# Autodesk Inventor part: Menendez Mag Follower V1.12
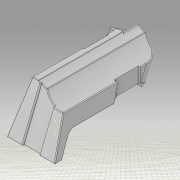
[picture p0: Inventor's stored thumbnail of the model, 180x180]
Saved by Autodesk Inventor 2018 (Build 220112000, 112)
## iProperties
Created: 2019-06
Part Number: Menendez Mag Follower V1.12
Material: Generic
Document SubType Name: Modeling
Designer: Ivan
Density: 1 g/cm^3
Appearance: Default
Author: Ivan
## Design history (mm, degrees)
sketch "Sketch1"
  geometry: L1 (0, 0)-(10.77, 0); L2 (10.77, 0)-(10.77, -30.556); L3 (10.77, -30.556)-(0, -30.556); L4 (0, -30.556)-(0, 0)
  constraints: 8 end point, 2 parallel, 1 horizontal, 1 perpendicular
  dimensions: "d0" = 10.7696 distance of L2.end L3.end; "d1" = 30.5562 distance of L1.end L2.end
extrude "Extrusion1" new body sketch "Sketch1" distance "d2" = 8.5344; taper "d3" = 0 deg
sketch "Sketch2"
  geometry: L1 (0, 0)-(3.287, 8.135); L2 (0, 0)-(8.774, 0); L3 (3.287, 8.135)-(3.448, 8.534); L4 (0, 8.534)-(30.556, 8.534) reference; L5 (30.556, 0)-(30.556, 8.534) reference; L6 (30.556, 8.534)-(27.343, 0.582); L7 (30.556, 8.534)-(39.133, 8.534); L8 (27.343, 0.582)-(27.108, 0); L9 (30.556, 0)-(0, 0) reference; L10 (0, 0)-(0, 8.534) reference; L11 (0, 8.534)-(0, 0)
  constraints: 14 end point, 4 point on line, 2 equal length, 2 horizontal, 1 collinear
  dimensions: "d4" = 68 deg angle of L2 L1; "d5" = 112 deg angle of L6 L7
workplane "Work Plane2"
workplane "Work Plane1"
sketch "Sketch7"
  geometry: L1 (30.556, -8.534)-(0, -8.534) reference; L2 (13.161, -8.534)-(13.161, -3.886); L3 (27.108, 0)-(30.556, -8.534) reference; L4 (27.108, 0)-(33.236, -15.167) reference; L5 (0, 0)-(30.556, 0) reference; L6 (13.161, -3.886)-(19.98, -3.886); L7 (16.616, 0)-(17.43, -2.015); L8 (17.43, -2.015)-(18.186, -3.886); L9 (30.556, 0)-(0, 0) reference; L10 (16.616, 0)-(27.108, 0); L11 (18.186, -3.886)-(28.678, -3.886); L12 (27.108, 0)-(28.678, -3.886); L13 (28.678, -3.886)-(12.524, -3.886); L14 (12.524, -3.886)-(12.885, -4.78); L15 (12.885, -4.78)-(14.232, -8.114); L16 (0, -8.534)-(30.556, -8.534) reference; L17 (14.402, -8.534)-(14.232, -8.114); L18 (14.402, -8.534)-(30.556, -8.534); L19 (30.556, -8.534)-(28.678, -3.886); 1 further point
  constraints: 26 end point, 5 collinear, 4 point on line, 3 parallel, 2 horizontal, 1 vertical
  dimensions: "d18" = 4.6482 distance of L2.start L2.end; "d20" = 16.1544 distance of L11.end L13.end
sketch "Sketch8"
  geometry: L1 (0, 8.534)-(10.77, 8.534) reference; L2 (5.385, 8.534)-(5.385, -8.103); L3 (5.385, -8.103)-(-2.515, -8.103); L4 (-2.515, -8.103)-(0, 8.534); L5 (-2.515, -8.103)-(0, 8.534); L6 (0, 8.534)-(5.385, 8.534); 1 further point
  constraints: 10 end point, 2 collinear, 1 midpoint, 1 perpendicular, 1 vertical
  dimensions: "d21" = 16.637 distance of L2.start L2.end; "d22" = 7.8994 distance of L2.end L3.end
extrude "Extrusion6" join sketch "Sketch8" distance "d23" = 19.558; taper "d24" = 0 deg
sketch "Sketch11"
  geometry: L1 (18.032, -1.719)-(27.922, -1.719); L2 (27.922, -1.719)-(27.922, 21.577); L3 (27.922, 21.577)-(18.032, 21.577); L4 (18.032, 21.577)-(18.032, -1.719); 1 further point
  constraints: 8 end point, 2 parallel, 1 horizontal, 1 perpendicular
extrude "Extrusion7" join sketch "Sketch11" distance "d25" = 16.129; taper "d26" = 0 deg
sketch "Sketch12"
  geometry: L1 (10.258, 5.653)-(-17.984, 5.653); L2 (-17.984, 5.653)-(-17.984, -21.463); L3 (-17.984, -21.463)-(10.258, -21.463); L4 (10.258, -21.463)-(10.258, 5.653); 1 further point
  constraints: 8 end point, 2 parallel, 1 horizontal, 1 perpendicular
extrude "Extrusion8" cut sketch "Sketch12" distance "d27" = 16.129; taper "d28" = 0 deg
sketch "Sketch13"
  geometry: L1 (-12.767, -9.49)-(31.439, -9.49); L2 (31.439, -9.49)-(31.439, 48.574); L3 (31.439, 48.574)-(-12.767, 48.574); L4 (-12.767, 48.574)-(-12.767, -9.49); 1 further point
  constraints: 8 end point, 2 parallel, 1 horizontal, 1 perpendicular
extrude "Extrusion9" cut sketch "Sketch13" distance "d29" = 16.129; taper "d30" = 0 deg
sketch "Sketch14"
  geometry: L1 (0, 0)-(8.413, 0) reference; L2 (8.413, 0)-(8.413, 8.103) reference; L3 (3.028, 8.103)-(8.413, 8.103) reference; L4 (3.028, 8.103)-(3.028, 16.637) reference; L5 (3.028, 16.637)-(-2.515, 16.637) reference; L6 (0, 0)-(-2.515, 16.637) reference; 1 further point
extrude "Extrusion10" cut sketch "Sketch14" distance "d31" = 16.129; taper "d32" = 0 deg
sketch "Sketch16"
  geometry: L1 (-6.479, 4.169)-(15.928, 4.169); L2 (15.928, 4.169)-(15.928, -19.738); L3 (15.928, -19.738)-(-6.479, -19.738); L4 (-6.479, -19.738)-(-6.479, 4.169); 1 further point
  constraints: 8 end point, 2 parallel, 1 horizontal, 1 perpendicular
extrude "Extrusion11" cut sketch "Sketch16" stored distance "d33" = 16.129; taper "d34" = 0 deg
sketch "Sketch18"
  geometry: L1 (-21.306, 0)-(-14.584, 16.637) reference; L2 (-21.306, 0)-(-19.147, 0); L3 (1.526, 0)-(-21.306, 0) reference; L4 (-17.563, 9.263)-(-14.69, 8.103); L5 (-18.032, 8.103)-(-21.306, 0) reference; L6 (12.524, 8.103)-(-18.032, 8.103) reference; L7 (-14.69, 8.103)-(-19.147, 0); L8 (-14.69, 8.103)-(0, 8.103); L9 (0, 8.103)-(0, 0) reference; L10 (0, 0)-(0, 8.103); L11 (0, 8.103)-(0, 0); L12 (0, 0)-(-19.147, 0)
  constraints: 14 end point, 4 point on line, 3 perpendicular, 1 collinear
  dimensions: "d35" = 2.159 distance of L1.start L2.end; "d36" = 3.0988 distance of L4.start L4.end
extrude "Extrusion12" cut sketch "Sketch18" distance "d37" = 16.129; taper "d38" = 0 deg
sketch "Sketch19"
  geometry: L1 (12.524, 0)-(27.214, 0) reference; L2 (27.108, 8.534)-(30.556, 0) reference; L3 (12.524, 4.445)-(28.76, 4.445); L4 (27.108, 8.534)-(0, 8.534) reference; L5 (26.182, 12.255)-(16.973, 8.534); L6 (16.973, 8.534)-(18.626, 4.445); L7 (16.973, 8.534)-(27.108, 8.534); L8 (27.108, 8.534)-(28.76, 4.445); L9 (16.973, 8.534)-(12.524, 8.534); L10 (12.524, 4.445)-(6.405, 4.445); L11 (11.337, 4.445)-(13.133, 0); L12 (0, 0)-(30.556, 0) reference; L13 (21.459, 8.534)-(26.315, 10.497); L14 (13.133, 0)-(10.5, 0); L15 (10.5, 0)-(10.5, 8.534); L16 (16.973, 8.534)-(10.5, 8.534); 1 further point
  constraints: 24 end point, 8 point on line, 4 perpendicular, 3 horizontal, 2 collinear, 2 parallel
  dimensions: "d39" = 4.445 distance of L1.start L3.start; "d40" = 9.9314 distance of L5.start L5.end; "d101" = 16.1544 distance of L11.start L13.end
extrude "Extrusion13" cut sketch "Sketch19" distance "d41" = 16.129; taper "d42" = 0 deg
extrude "Extrusion14" cut sketch "Sketch2" distance "d43" = 25.4; taper "d44" = 0 deg
workplane "Work Plane3"
mirror "Mirror1"
sketch "Sketch20"
  geometry: L1 (0, 0)-(1.115, -2.026) reference; L2 (3.274, -2.026)-(1.115, -2.026) reference; L3 (3.274, -2.026)-(0, 6.076) reference; L4 (0, 0)-(0, 6.076) reference; 1 further point
extrude "Extrusion15" join sketch "Sketch20" stored distance "d45" = 25.4; taper "d46" = 0 deg
sketch "Sketch21"
  geometry: L1 (12.894, 0.193)-(12.894, 0) reference; L2 (12.894, 0)-(16.342, 8.631); L3 (12.894, 0)-(14.69, 4.495) reference; L4 (8.588, 4.495)-(14.69, 4.495); L5 (15.877, 4.588)-(8.588, 4.588) reference; L6 (10.241, 8.631)-(16.342, 8.631); L7 (15.877, 4.495)-(8.588, 4.495) reference; L8 (8.588, 4.495)-(14.69, 4.495); L9 (14.69, 4.495)-(16.342, 8.631); L10 (16.342, 8.631)-(10.241, 8.631); L11 (8.588, 4.495)-(7.662, 4.495); L12 (7.662, 4.495)-(9.218, 8.631); L13 (0.106, 8.631)-(10.241, 8.631) reference; L14 (10.241, 8.631)-(9.218, 8.631); 6 further points; 1 other entity
  constraints: 18 end point, 3 horizontal, 3 parallel, 1 collinear, 1 point on line, 2 other
extrude "Extrusion16" join sketch "Sketch21" stored distance "d47" = 25.4; taper "d48" = 0 deg
sketch "Sketch22"
  geometry: L1 (1.758, 4.352)-(1.796, 4.445) reference; L2 (0, 0)-(1.796, 4.445) reference; L3 (0, 0)-(1.758, 4.352) reference; L4 (0, 0)-(1.796, 4.445) reference; L5 (0, 0)-(4.134, 10.233); L6 (4.134, 10.233)-(4.816, 9.16); L7 (4.816, 9.16)-(4.134, 2.45); L8 (1.187, 0)-(-12.894, 0) reference; L9 (4.134, 2.45)-(0, 0); 2 further points
  constraints: 8 end point, 1 collinear
extrude "Extrusion17" cut sketch "Sketch22" distance "d49" = 25.4; taper "d50" = 0 deg
workplane "Work Plane4"
sketch "Sketch23"
  geometry: L1 (-5.715, -4.089)-(-5.715, 0) reference; L2 (-5.715, 0)-(-3.683, 0); L3 (-5.715, 0)-(5.055, 0) reference; L4 (-3.683, 0)-(-3.683, -1.016); L5 (-3.683, -1.016)-(-1.016, -1.016); L6 (-1.016, -1.016)-(-1.016, -3.556); L7 (6.345, -8.534)-(5.055, 0) reference; L8 (5.592, -3.556)-(5.055, 0); L9 (5.055, 0)-(-3.683, 0); L10 (5.055, 0)-(-5.715, 0) reference; A1 r 4.215 centre (-0.938, 3.198) between (-3.683, 0) and (-1.016, -1.016); A2 r 6.35 centre (4.18, 2.635) between (-1.016, -1.016) and (5.592, -3.556); 2 further points
  constraints: 12 end point, 4 point on circle, 2 centre point, 2 collinear, 2 perpendicular, 2 point on line, 1 vertical
  dimensions: "d52" = 2.032 distance of L1.end L2.end; "d53" = 1.016 distance of L2.end L4.end; "d54" = 2.667 distance of L4.end L5.end; "d55" = 2.54 distance of L5.end L6.end; "d56" = 6.35 radius of A2
extrude "Extrusion18" cut sketch "Sketch23" stored distance "d57" = 76.2; taper "d58" = 0 deg
fillet "Fillet1" dims "d59" = 1.016
sketch "Sketch25"
  geometry: L1 (9.054, -4.88)-(9.054, -8.08) reference; L2 (9.054, -4.88)-(6.98, -10.013); L3 (9.054, -4.88)-(11.026, 0) reference; L4 (7.761, -8.08)-(9.054, -8.08); L5 (9.054, -4.88)-(8.013, -4.88) reference; L6 (9.054, -4.88)-(9.054, -8.08); L7 (7.761, -8.08)-(3.392, -8.08); L8 (3.392, -8.08)-(4.685, -4.88); L9 (9.054, -4.88)-(-0.631, -4.88) reference; L10 (-0.631, -4.88)-(9.054, -4.88) reference; L11 (4.685, -4.88)-(9.054, -4.88); 3 further points
  constraints: 12 end point, 3 collinear, 2 horizontal, 2 point on line, 1 parallel
  dimensions: "d66" = 4.3688 distance of L4.start L7.end
sketch "Sketch26"
  geometry: 1 further point
extrude "Extrusion20" join sketch "Sketch25" stored distance "d67" = 10.16; taper "d68" = 0 deg
sketch "Sketch27"
  geometry: L1 (3.392, -8.08)-(7.761, -8.08) reference; L2 (7.761, -8.08)-(6.72, -8.08); L3 (-0.631, -4.88)-(4.685, -4.88) reference; L4 (4.685, -4.88)-(3.392, -8.08); A1 r 3.227 centre (3.499, -7.881) between (6.72, -8.08) and (4.685, -4.88); 3 further points
  constraints: 4 end point, 2 point on circle, 1 centre point, 1 point on line
  dimensions: "d69" = 1.0414 distance of L1.end L2.end
extrude "Extrusion21" cut sketch "Sketch27" stored distance "d70" = 10.16; taper "d71" = 0 deg
workplane "Work Plane5"
sketch "Sketch32"
  geometry: L1 (-8.737, 0)-(6.64, 0) reference; L2 (-1.048, 0)-(1.492, 0); L3 (1.492, 0)-(-3.588, 0); L4 (-3.588, 0)-(-3.588, -0.381); L5 (1.492, 0)-(1.492, -0.381); L6 (1.492, -0.381)-(-3.588, -0.381); 3 further points
  constraints: 10 end point, 2 perpendicular, 2 point on line, 1 midpoint, 1 vertical
  dimensions: "d86" = 2.54 distance of L2.start L2.end; "d87" = 5.08 distance of L2.end L3.end; "d88" = 0.381 distance of L3.end L4.end
extrude "Extrusion26" cut sketch "Sketch32" stored distance "d89" = 50.8; taper "d90" = 0 deg
fillet "Fillet3" dims "d91" = 0.3556
workplane "Work Plane6"
sketch "Sketch36"
  geometry: L1 (-0.044, -8.686)-(1.937, -8.686); L2 (1.937, -8.686)-(1.937, 0); L3 (1.937, 0)-(-0.044, 0); L4 (-0.044, 0)-(-0.044, -8.686); 1 further point
  constraints: 8 end point, 2 parallel, 1 horizontal, 1 perpendicular
extrude "Extrusion29" cut sketch "Sketch36" stored distance "d102" = 50.8; taper "d103" = 0 deg
sketch "Sketch37"
  geometry: L1 (-0.785, -4.88)-(-0.411, -3.955) reference; L2 (-0.785, -4.88)-(1.189, 0.005); L3 (-1.972, -4.88)-(0.04, 0.099) reference; L4 (0.04, 0.099)-(-16.197, 0.099) reference; L5 (0.04, 0.099)-(1.226, 0.099); L6 (1.226, 0.099)-(1.189, 0.005); L7 (0, 0)-(-1.972, -4.88) reference; L8 (0.04, 0.099)-(-1.972, -4.88); L9 (-0.785, -4.88)-(-1.972, -4.88); L10 (-0.785, -4.88)-(-14.866, -4.88) reference; 1 further point
  constraints: 10 end point, 2 collinear, 1 horizontal, 1 parallel
extrude "Extrusion30" join sketch "Sketch37" stored distance "d104" = 50.8; taper "d105" = 0 deg
sketch "Sketch39"
  geometry: L1 (5.055, -3.556)-(5.592, -3.556) reference; L2 (5.055, -3.556)-(5.055, -3.655) reference; A1 r 6.35 centre (4.18, 2.635) between (5.055, -3.655) and (5.592, -3.556) reference; 1 further point
extrude "Extrusion31" cut sketch "Sketch39" stored distance "d106" = 50.8; taper "d107" = 0 deg
workplane "Work Plane7"
sketch "Sketch40"
  geometry: L1 (0, 0)-(0, -8.08) reference; L2 (0, 0)-(10.77, 0) reference; L3 (10.77, -11.735)-(10.77, 0) reference; L4 (8.738, -11.735)-(10.77, -11.735) reference; A1 r 6.35 centre (0.875, -14.37) between (6.071, -10.719) and (0, -8.08) reference; A2 r 4.215 centre (5.992, -14.933) between (8.738, -11.735) and (6.071, -10.719) reference; 1 further point
extrude "Extrusion32" join sketch "Sketch40" distance "d109" = 50.8; taper "d110" = 0 deg
sketch "Sketch41"
  geometry: L1 (-15.412, 4.978)-(-20.132, -6.706) reference; L2 (-17.423, 0)-(9.895, -11.037); L3 (9.895, -11.037)-(23.131, 21.723); L4 (23.131, 21.723)-(63.294, 20.181); L5 (63.294, 20.181)-(80.698, -6.696); L6 (80.698, -6.696)-(73.206, -14.512); L7 (73.206, -14.512)-(25.524, -20.796); L8 (25.524, -20.796)-(9.895, -11.037)
  constraints: 14 end point, 2 perpendicular
  dimensions: "d111" = 29.464 distance of L2.start L2.end
extrude "Extrusion33" cut sketch "Sketch41" stored distance "d112" = 50.8; taper "d113" = 0 deg
sketch "Sketch42"
  geometry: L1 (7.351, -3.2)-(13.062, -3.2) reference; L2 (13.062, -3.2)-(12.02, -3.2); L3 (7.351, -3.2)-(11.64, -3.2); L4 (10.073, 0)-(5.316, 0); A1 r 3.227 centre (4.13, -3.001) between (7.351, -3.2) and (5.316, 0) reference; A2 r 3.175 centre (8.857, -2.933) between (12.02, -3.2) and (10.073, 0); 1 further point
  constraints: 6 end point, 2 horizontal, 2 point on circle, 1 centre point, 1 point on line
  dimensions: "d114" = 1.0414 distance of L1.end L2.end; "d115" = 3.175 radius of A2
extrude "Extrusion34" cut sketch "Sketch42" distance "d116" = 50.8; taper "d117" = 0 deg
sketch "Sketch43"
  geometry: 1 further point
sketch "Sketch44"
  geometry: L1 (6.851, -1.397)-(-8.948, -1.397) reference; L2 (-1.048, -1.046)-(-1.048, -28.498); L3 (-6.433, -28.498)-(4.336, -28.498) reference; L4 (-6.433, -25.494)-(-6.433, -16.154) reference; L5 (-6.433, -20.216)-(-5.392, -20.216); L6 (-5.392, -20.216)-(-5.392, -24.454); L7 (-5.392, -24.454)-(-5.392, -3.099); L8 (-7.723, -3.099)-(5.626, -3.099) reference; A1 r 6.35 centre (-0.708, -7.387) between (-1.048, -1.046) and (-5.392, -3.099); A2 r 6.35 centre (0.606, -22.368) between (-5.392, -24.454) and (-1.048, -28.498); 1 further point
  constraints: 8 end point, 4 point on circle, 3 point on line, 2 centre point, 1 midpoint, 1 perpendicular, 1 vertical
  dimensions: "d118" = 6.35 radius of A1; "d119" = 27.45233 distance of L2.end L2.start; "d120" = 6.35 radius of A2; "d148" = 1.0414 distance of L5.start L5.end
extrude "Extrusion35" cut sketch "Sketch44" stored distance "d121" = 50.8; taper "d122" = 0 deg
mirror "Mirror5"
sketch "Sketch45"
  geometry: L1 (-2.106, 2.085)-(4.203, 2.085) reference; A1 r 6.35 centre (1.388, 7.387) between (-2.106, 2.085) and (1.048, 1.046) reference; A2 r 6.35 centre (0.708, 7.387) between (1.048, 1.046) and (4.203, 2.085) reference; 1 further point
extrude "Extrusion36" cut sketch "Sketch45" distance "d123" = 50.8; taper "d124" = 0 deg
fillet "Fillet4" dims "d125" = 2.54
sketch "Sketch46"
  geometry: L1 (-11.266, -7.645)-(-14.531, 0.435) reference; L2 (-13.683, -1.662)-(-15.358, 2.483); L3 (-11.213, 4.157)-(-7.737, -4.445); L4 (1.796, -4.445)-(-8.277, -4.445) reference; L5 (15.771, 4.089)-(-16.007, 4.089) reference; L6 (-11.186, 4.089)-(-16.007, 4.089); L7 (-10.225, -7.645)-(-11.266, -7.645) reference; L8 (-16.007, 4.089)-(-11.266, -7.645); L9 (-11.266, -7.645)-(-10.225, -7.645); L10 (-7.737, -4.445)-(-8.277, -4.445); A1 r 3.175 centre (-7.061, -7.378) between (-8.277, -4.445) and (-10.225, -7.645); 1 further point
  constraints: 12 end point, 4 collinear, 4 point on line, 2 point on circle, 1 centre point
  dimensions: "d126" = 4.4704 distance of L2.start L2.end; "d127" = 4.4704 distance of L2.end L3.start
extrude "Extrusion37" join sketch "Sketch46" distance "d128" = 2.2098; taper "d129" = 0 deg
sketch "Sketch47"
  geometry: L1 (-10.77, 13.583)-(-10.77, 30.405) reference; L2 (-10.77, 30.405)-(-8.738, 30.405); L3 (-12.979, 30.485)-(0, 30.485) reference; L4 (-10.77, 30.405)-(-8.738, 30.405); L5 (-8.738, 3.448)-(-8.738, 35.226) reference; L6 (-8.738, 30.405)-(-8.738, 35.226); L7 (-12.979, 35.226)-(-12.979, 30.485) reference; L8 (-8.738, 35.226)-(-12.979, 35.226); L9 (-12.979, 35.226)-(-12.979, 30.405); L10 (-8.738, 35.226)-(-8.738, 30.908); L11 (-12.979, 30.405)-(-8.738, 30.405); L12 (-8.738, 30.405)-(-8.738, 35.226); L13 (-8.738, 35.226)-(-12.979, 35.226); L14 (-12.979, 35.226)-(-12.979, 30.405); 1 further point
  constraints: 20 end point, 3 parallel, 2 collinear, 2 horizontal, 2 point on line, 1 perpendicular
  dimensions: "d130" = 2.032 distance of L1.end L2.end; "d131" = 0 distance between parallel lines of L2 L4 (derived); "d132" = 4.318 distance of L5.end L10.end
workplane "Work Plane9"
  workplane "Work Plane8"
extrude "Extrusion38" cut sketch "Sketch47" stored distance "d135" = 1.778; taper "d136" = 0 deg
sketch "Sketch48"
  geometry: L1 (3.448, -7.332)-(0, 1.202) reference; L2 (0, 1.202)-(0, 0) reference; L3 (0, 0)-(0.418, 0.169); L4 (0, 1.202)-(0.406, 0.198); L5 (0.418, 0.169)-(0.371, 0.284); L6 (0, 1.202)-(-4.821, 1.202) reference; L7 (0, 1.202)-(0, 0); 1 further point
  constraints: 8 end point, 3 point on line, 2 perpendicular
extrude "Extrusion39" cut sketch "Sketch48" distance "d137" = 25.4; taper "d138" = 0 deg
fillet "Fillet5" dims "d139" = 4.572
fillet "Fillet7" dims "d141" = 0.254
fillet "Fillet8" dims "d142" = 0.254
fillet "Fillet9" dims "d143" = 0.254
sketch "Sketch49"
  geometry: L1 (-23.949, -12.767)-(-17.284, -12.767); L2 (-17.284, -12.767)-(-17.284, -10.862); L3 (-17.284, -10.862)-(-23.949, -10.862); L4 (-23.949, -10.862)-(-23.949, -12.767); 1 further point
  constraints: 8 end point, 2 parallel, 1 horizontal, 1 perpendicular
  dimensions: "d144" = 1.905 distance of L2.end L1.end
extrude "Extrusion40" cut sketch "Sketch49" stored distance "d145" = 27.94; taper "d146" = 0 deg
fillet "Fillet10" dims "d147" = 0.254
sketch "Sketch50"
  geometry: L1 (-0.254, 0)-(-0.254, -0.254) reference; L2 (1.778, 0)-(0, 0) reference; L3 (1.778, 0)-(1.778, 4.459) reference; L4 (-0.254, 0)-(-2.464, 0) reference; A1 r 0.254 centre (0, -0.254) between (0, 0) and (-0.254, -0.254) reference; A2 r 4.572 centre (2.107, -0.102) between (1.778, 4.459) and (-2.464, 0) reference; 1 further point
extrude "Extrusion41" cut sketch "Sketch50" distance "d149" = 0.508; taper "d150" = 0 deg
fillet "Fillet11" dims "d151" = 0.254
sketch "Sketch51"
  geometry: L1 (0, -19.253)-(-0.635, -19.253); L2 (-0.635, -19.253)-(-0.635, -26.95); L3 (-0.635, -26.95)-(0, -26.95); L4 (0, -26.95)-(0, -19.253); 3 further points; 1 other entity
  constraints: 8 end point, 2 parallel, 1 horizontal, 1 perpendicular, 1 other
  dimensions: "d152" = 0.635 distance of L3.end L2.end
extrude "Extrusion42" cut sketch "Sketch51" distance "d153" = 25.4; taper "d154" = 0 deg
mirror "Mirror6"
fillet "Fillet12" dims "d157" = 0.5334
fillet "Fillet13" dims "d158" = 0.381
sketch "Sketch53"
  geometry: L1 (-0.254, 0)-(-2.196, 0) reference; L2 (-0.254, -0.254)-(-0.254, 0) reference; L3 (1.778, 0)-(0, 0) reference; L4 (1.778, 4.459)-(1.778, 0) reference; A1 r 0.254 centre (-2.196, 0.254) between (-2.449, 0.275) and (-2.196, 0) reference; A2 r 0.254 centre (0, -0.254) between (0, 0) and (-0.254, -0.254) reference; A3 r 4.572 centre (2.107, -0.102) between (1.778, 4.459) and (-2.449, 0.275) reference; 1 further point
extrude "Extrusion44" join sketch "Sketch53" distance "d159" = 0.508; taper "d160" = 0 deg
sketch "Sketch54"
  geometry: L1 (-9.728, -4.645)-(-9.728, -27.671) reference; L2 (-9.728, -13.237)-(-8.392, -13.237); L3 (-8.392, -13.237)-(-8.392, -4.645); L4 (-8.392, -4.645)-(-9.728, -4.645); L5 (-9.728, -4.645)-(-9.728, -13.237); A1 r 7.614 centre (-3.441, -8.941) between (-9.728, -4.645) and (-9.728, -13.237); 1 further point
  constraints: 8 end point, 2 parallel, 2 point on circle, 1 centre point, 1 horizontal, 1 perpendicular, 1 point on line
extrude "Extrusion45" cut sketch "Sketch54" stored distance "d162" = 0.508; taper "d163" = 0 deg
fillet "Fillet14" dims "d164" = 0.254
body "Solid1"
node "Projected Loop1"
node "Projected Loop2"
node "Projected Loop3"
node "Projected Loop7"
node "Projected Loop8"
node "Projected Loop9"
node "Projected Loop10"
node "Projected Loop12"
other parameters: "d51" = 90 deg, "d81" = 90 deg, "d94" = -3.4798, "d108" = 90 deg, "d133" = 90 deg, "d134" = 2.921
